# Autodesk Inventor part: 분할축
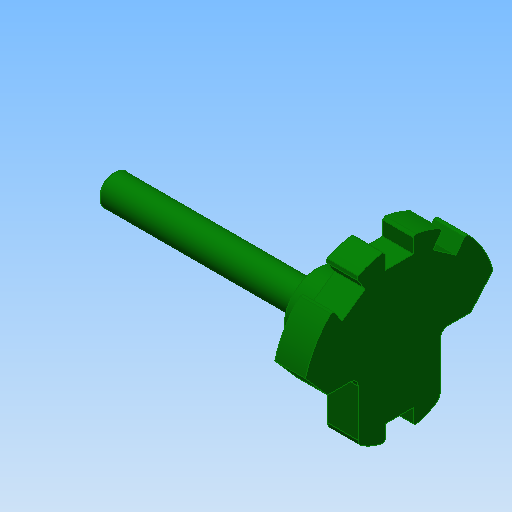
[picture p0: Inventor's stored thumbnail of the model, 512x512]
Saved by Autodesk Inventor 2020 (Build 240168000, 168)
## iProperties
Created: 2016-11
Part Number: 분할축
Material: 강철, 연강
Document SubType Name: Modeling
Designer: mduedu
Density: 1 g/cm^3
Appearance: 진녹색
Author: mduedu
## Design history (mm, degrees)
sketch "스케치1"
  geometry: C1 r 38 at (0, 0); 1 further point
  constraints: 1 centre point, 1 coincident
  dimensions: "d0" = 76 diameter of C1
extrude "돌출1" new body sketch "스케치1" distance "d1" = 12; taper "d2" = 0 deg
sketch "스케치2"
  geometry: L1 (0, 38)-(0, -38); L2 (5.5, 37.6)-(5.5, 31); L3 (5.5, 31)-(-5.5, 31); L4 (-5.5, 31)-(-5.5, 37.6); A1 r 38 centre (0, 0) between (0, 38) and (0, -38) reference; A2 r 38 centre (0, 0) between (5.5, 37.6) and (-5.5, 37.6); 2 further points
  constraints: 8 end point, 6 point on circle, 2 coincident, 2 vertical, 1 centre point, 1 horizontal, 1 midpoint, 1 parallel, 1 symmetric about line
  dimensions: "d3" = 11 distance of L2.end L3.end; "d5" = 31 distance from line of L3 point (0, 0)
extrude "돌출2" cut sketch "스케치2" extent not by distance; stored distance "d7" = 12; taper "d8" = 0 deg
sketch "스케치3"
  geometry: L1 (-16, 0)-(-38, 0); L2 (16, 0)-(38, 0); L3 (0, -28)-(0, 28); L4 (-16, -22.978)-(-16, 0); L5 (16, -22.978)-(16, 0); A1 r 38 centre (0, 0) between (-5.5, 37.6) and (-17.061, 33.955) reference; A2 r 38 centre (0, 0) between (-38, 0) and (38, 0); A3 r 28 centre (0, 0) between (-16, -22.978) and (16, -22.978); 4 further points
  constraints: 10 end point, 7 point on circle, 3 coincident, 2 centre point, 2 horizontal alignment, 2 midpoint, 2 parallel, 1 collinear, 1 horizontal, 1 perpendicular, 1 other
  dimensions: "d13" = 32 distance between parallel lines of L5 L4; "d14" = 28 radius of A3
extrude "돌출3" cut sketch "스케치3" extent not by distance; stored distance "d15" = 12; taper "d16" = 0 deg
sketch "스케치4"
  geometry: L1 (0, 0)-(0, -28); L2 (5.5, -27.455)-(5.5, -21); L3 (5.5, -21)-(-5.5, -21); L4 (-5.5, -21)-(-5.5, -27.455); A1 r 28 centre (0, 0) between (-16, -22.978) and (16, -22.978) reference; A2 r 28 centre (0, 0) between (16, -22.978) and (0, -28); A3 r 28 centre (0, 0) between (-5.5, -27.455) and (5.5, -27.455); 1 further point
  constraints: 8 end point, 7 point on circle, 2 centre point, 2 coincident, 1 horizontal, 1 parallel, 1 other
  dimensions: "d17" = 11 distance between parallel lines of L2 L4; "d19" = 21 distance from line of L3 point (0, 0)
extrude "돌출4" cut sketch "스케치4" extent not by distance; stored distance "d20" = 12; taper "d21" = 0 deg
sketch "스케치5"
  geometry: C1 r 13 at (0, 0); 1 further point
  constraints: 1 centre point, 1 coincident
  dimensions: "d22" = 26 diameter of C1
extrude "돌출5" join sketch "스케치5" distance "d23" = 20; taper "d24" = 0 deg
sketch "스케치6"
  geometry: C1 r 6 at (0, 0); 1 further point
  constraints: 1 centre point, 1 coincident
  dimensions: "d25" = 12 diameter of C1
extrude "돌출6" join sketch "스케치6" distance "d26" = 80; taper "d27" = 0 deg
fillet "모깎기1" dims "d28" = 3
chamfer "모따기1" distance "d29" = 1; stored, may be unused: second distance "d30" = 2, angle "d31" = 45 deg
sketch "스케치7"
  geometry: L1 (-20, 13)-(-20, -13) reference; L2 (-20, 6)-(-99, 6) reference; L3 (0, 0)-(-20, 0); C1 r 1 at (-21, 6)
  constraints: 2 end point, 1 centre point, 1 midpoint, 1 tangent
  dimensions: "d32" = 2 diameter of C1; "d33" = 10 dimension on C1 L3
revolve "회전1" sketch "스케치7" stored, may be unused: angle "d34" = 90 deg
chamfer "모따기2" distance "d35" = 1; stored, may be unused: second distance "d36" = 2, angle "d37" = 45 deg
chamfer "모따기3" distance "d38" = 10; stored, may be unused: second distance "d39" = 2, angle "d40" = 45 deg
chamfer "모따기4" distance "d41" = 1; stored, may be unused: second distance "d42" = 2, angle "d43" = 45 deg
fillet "모깎기2" dims "d44" = 3
node "솔리드1"
pattern_circular "원형 패턴1" dims angle "d10" = 35 deg
other parameters: "d12" = 56
